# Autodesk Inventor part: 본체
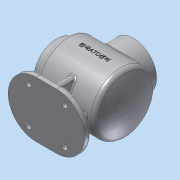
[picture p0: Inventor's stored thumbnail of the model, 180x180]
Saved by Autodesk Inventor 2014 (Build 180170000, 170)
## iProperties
Created: 2023-01
Part Number: 본체
Material: 알루미늄 6061
Document SubType Name: Modeling
Designer: dg
Density: 2.71 g/cm^3
Appearance: 알루미늄 - 평지
Mass: 1038.22 g
Surface Area: 1157.5 cm^2
Volume: 383.109 cm^3
Author: dg
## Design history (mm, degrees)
sketch "스케치1"
  geometry: L1 (0, 0)-(0, 38); L2 (0, 38)-(12, 38); L3 (12, 38)-(12, 50); L4 (12, 50)-(111.087, 50); L5 (0, 0)-(122, 0); L6 (0, 27)-(17, 27); L7 (17, 27)-(17, 45); L8 (17, 45)-(107.83, 45); A1 r 120 centre (2, 0) between (122, 0) and (111.087, 50); A2 r 115 centre (2, 0) between (117, 0) and (107.83, 45)
  constraints: 17 end point, 4 point on circle, 3 parallel, 3 perpendicular, 2 centre point, 2 point on line, 1 concentric, 1 horizontal, 1 vertical
  dimensions: "d1" = 54 diameter of L6 L5; "d2" = 76 diameter of L2 L5; "d3" = 100 diameter of L4 L5; "d4" = 17 distance of L6.start L6.end; "d6" = 5 radial gap between concentric circles of A1 A2; "d7" = 90 diameter of L8 L5; "d8" = 120 radius of A1; "d9" = 122 distance from line of L5.end L1; "d10" = 5 distance between parallel lines of L3 L7; "d11" = 117 distance from line of L1 A2.start
revolve "회전1" sketch "스케치1" stored, may be unused: angle "d12" = 90 deg
node "작업 평면1"
sketch "스케치2"
  geometry: L1 (-80, 0)-(-46, 0); L2 (-80, -46)-(-46, -46); L3 (-46, 46)-(-80, 46); L4 (-58, 35)-(-68, 35); L5 (-68, 35)-(-68, -35); L6 (-68, -35)-(-58, -35); L7 (-58, -35)-(-58, 35); L8 (0, 38)-(0, -38) reference; A1 r 46 centre (-80, 0) between (-80, 46) and (-80, -46); A2 r 46 centre (-46, 0) between (-46, -46) and (-46, 46); 8 further points
  constraints: 16 end point, 6 midpoint, 6 point on circle, 4 tangent, 3 parallel, 2 centre point, 2 horizontal, 1 coincident, 1 horizontal alignment, 1 perpendicular, 1 vertical alignment
  dimensions: "d14" = 10 distance of L4.start L4.end; "d15" = 70 distance of L4.end L5.end; "d16" = 92 distance between parallel lines of L2 L3; "d17" = 126 distance of point (0, 0) point (-126, 0)
extrude "돌출1" join sketch "스케치2" distance "d21" = 10; taper "d22" = 0 deg
extrude "돌출2" join sketch "스케치2" stored distance "d23" = 10; taper "d24" = 0 deg
sketch "스케치3"
  geometry: L1 (111.087, -50)-(111.087, 50) reference; L2 (12, -50)-(12, 50) reference; L3 (58, -35.707)-(58, -35.707) reference; L4 (58, -35.707)-(68, -35.707) reference; L5 (68, -35.707)-(68, -35.707) reference; L6 (68, -35.707)-(58, -35.707) reference; L7 (12, -50)-(111.087, -50) reference; L8 (46, -70)-(0, -70) reference; L9 (80, -70)-(46, -70) reference; L10 (126, -70)-(80, -70) reference; L11 (12, -50)-(111.087, -50) reference; L12 (28.359, -50)-(23, -70); L13 (97.641, -50)-(103, -70); L14 (28.359, -50)-(97.641, -50); 3 further points
  constraints: 6 end point, 4 midpoint, 2 point on line, 1 collinear, 1 vertical alignment
  dimensions: "d25" = 105 deg angle of L8 L12; "d26" = 105 deg angle of L10 L13; "d27" = 80 distance of L13.end L12.end
  node "투영된 루프1"
feature "리브1" dims "d28" = 1, "d29" = 10, "d30" = 0, "d31" = 0, "d32" = 1, "d33" = 1
feature "리브2" dims "d34" = 1, "d35" = 10, "d36" = 0, "d37" = 0, "d38" = 1, "d39" = 1
node "작업 평면2"
sketch "스케치4"
  geometry: L1 (-80, -46)-(-46, -46) reference; C1 r 38 at (-63, 0); C2 r 27 at (-63, 0); 2 further points
  constraints: 2 centre point, 1 coincident, 1 horizontal alignment, 1 midpoint, 1 vertical alignment
  dimensions: "d41" = 54 diameter of C2; "d42" = 76 diameter of C1
extrude "돌출3" join sketch "스케치4" stored distance "d43" = 10; taper "d44" = 0 deg
extrude "돌출4" cut sketch "스케치4" stored distance "d45" = 10; taper "d46" = 0 deg
sketch "스케치5"
  geometry: C1 r 38 at (0, 0) reference; 1 further point
  constraints: 1 vertical alignment
  dimensions: "d47" = 32.5 distance of C1.centre point (0, 32.5)
hole "구멍1" sketch "스케치5" at (0, 32.5) diameter "d48" = 3.242; stored, may be unused: countersink angle "d52" = 90 deg, drill point angle "d54" = 118 deg; dims "d49" = 8, "d50" = 4, "d51" = 2, "d53" = 10
sketch "스케치6"
  geometry: C1 r 27 at (0, 0) reference; 2 further points
  constraints: 1 vertical alignment
  dimensions: "d58" = 32.5 distance of C1.centre point (0, 32.5)
sketch "스케치7"
  geometry: L1 (58, 35)-(68, 35) reference; C1 r 4.5 at (33, 30); A1 r 46 centre (46, 0) between (46, 46) and (46, -46) reference; 2 further points
  constraints: 1 centre point, 1 midpoint
  dimensions: "d59" = 9 diameter of C1; "d60" = 30 horizontal distance of C1.centre point (63, 35); "d61" = 30 vertical distance of A1.centre C1.centre
extrude "돌출5" cut sketch "스케치7" stored distance "d62" = 10; taper "d63" = 0 deg
fillet "모깎기1" dims "d67" = 3
fillet "모깎기3" dims "d69" = 8
chamfer "모따기1" distance "d70" = 1; stored, may be unused: second distance "d71" = 2, angle "d72" = 45 deg
hole "구멍2" sketch "스케치6" diameter "d73" = 3.242; stored, may be unused: countersink angle "d77" = 90 deg, drill point angle "d79" = 118 deg; dims "d74" = 8, "d75" = 4, "d76" = 2, "d78" = 10
sketch "스케치8"
  geometry: 1 further point
fillet "모깎기4" dims "d83" = 3
node "작업 평면3"
sketch "스케치9"
  geometry: L1 (-15.544, -80)-(18.456, -80) reference; L2 (-61.544, -38)-(-61.544, 38) reference; 2 further points
  constraints: 1 other
  dimensions: "d84" = 80 distance from line of L1 point (1.456, 0); "d85" = 63 distance from line of point (1.456, 0) L2
feature "엠보싱1" sketch "스케치9" dims "d86" = 0.5, "d87" = 0
node "솔리드1"
pattern_circular "원형 패턴1" dims angle "d56" = 360 deg
pattern_circular "원형 패턴2" dims angle "d65" = 360 deg
pattern_circular "원형 패턴3" dims angle "d81" = 360 deg
other parameters: "d40" = 64
